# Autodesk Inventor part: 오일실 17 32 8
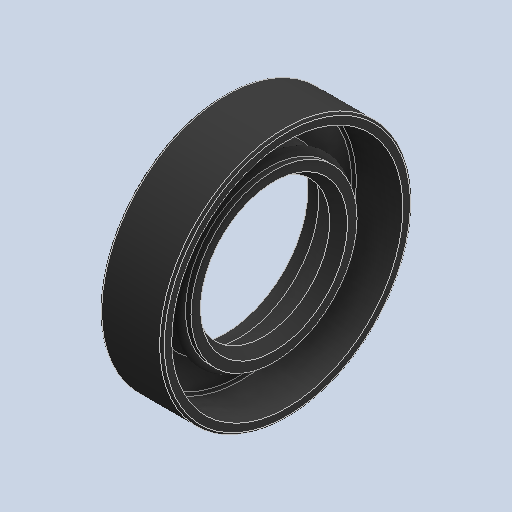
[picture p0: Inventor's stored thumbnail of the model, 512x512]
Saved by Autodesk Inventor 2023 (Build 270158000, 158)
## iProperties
Created: 2024-09
Part Number: 오일실 17 32 8
Material: 고무
Description: 오일-실
Document SubType Name: Modeling
Designer: home
Density: 0.93 g/cm^3
Appearance: 기본값
Author: jhkim
Sending System: Autodesk Inventor 2025
Preprocessor: ST-DEVELOPER v20
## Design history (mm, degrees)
feature "Solid1"
node "솔리드1"
